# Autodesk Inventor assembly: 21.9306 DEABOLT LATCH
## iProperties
Created: 2012-07
Part Number: 21.9306 DEABOLT LATCH
Document SubType Name: Assembly
Designer: Administrator
Mass: 132.838 g
Surface Area: 153.647 cm^2
Volume: 20.0341 cm^3
Density: 6.63061 g/cm^3
Author: Administrator
